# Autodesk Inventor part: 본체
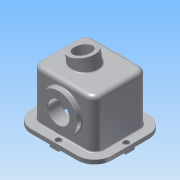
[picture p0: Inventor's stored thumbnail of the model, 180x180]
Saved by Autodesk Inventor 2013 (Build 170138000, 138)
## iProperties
Created: 2014-11
Part Number: 본체
Material: Aluminum 6061
Document SubType Name: Modeling
Designer: Administrator
Density: 2.71 g/cm^3
Mass: 2881.87 g
Surface Area: 2079.03 cm^2
Volume: 1063.42 cm^3
Author: Administrator
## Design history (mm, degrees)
sketch "Sketch1"
  geometry: L1 (-76, 65)-(76, 65); L2 (76, 65)-(76, -65); L3 (76, -65)-(-76, -65); L4 (-76, -65)-(-76, 65); L5 (-76, 65)-(76, -65); L6 (76, 65)-(-76, -65); 1 further point
  constraints: 12 end point, 2 midpoint, 2 parallel, 1 horizontal, 1 perpendicular
  dimensions: "d0" = 152 distance of L2.end L3.end; "d1" = 130 distance of L1.end L2.end
extrude "Extrusion1" new body sketch "Sketch1" distance "d2" = 60; taper "d3" = 0 deg; dims "d88" = 58, "d89" = 0
fillet "Fillet1" dims "d4" = 20
fillet "Fillet2" dims "d5" = 10
shell "Shell1" dims "d6" = 10
sketch "Sketch2"
  geometry: L1 (-66, -45)-(-66, 45) reference; L2 (-56, 55)-(56, 55) reference; L3 (66, 45)-(66, -45) reference; L4 (56, -55)-(-56, -55) reference; L5 (56, 87)-(-56, 87); L6 (-98, 45)-(-98, -45); L7 (-56, -87)-(56, -87); L8 (98, -45)-(98, 45); L9 (98, 87)-(-98, -87); L10 (-98, 87)-(98, -87); A1 r 10 centre (-56, 45) between (-56, 55) and (-66, 45) reference; A2 r 10 centre (56, 45) between (66, 45) and (56, 55) reference; A3 r 10 centre (56, -45) between (56, -55) and (66, -45) reference; A4 r 10 centre (-56, -45) between (-66, -45) and (-56, -55) reference; A5 r 42 centre (56, 45) between (98, 45) and (56, 87); A6 r 42 centre (56, -45) between (56, -87) and (98, -45); A7 r 42 centre (-56, -45) between (-98, -45) and (-56, -87); A8 r 42 centre (-56, 45) between (-56, 87) and (-98, 45); 3 further points
  constraints: 12 end point, 8 point on circle, 8 point on line, 8 tangent, 4 centre point, 3 equal radius, 3 midpoint, 2 parallel, 1 horizontal, 1 horizontal alignment, 1 perpendicular
  dimensions: "d7" = 196 distance of L9.end L10.end; "d9" = 174 distance of L10.start L9.end; "d10" = 42 radius of A5; "d11" = 10 distance from line of point (88, 0) L8
extrude "Extrusion2" join sketch "Sketch2" distance "d12" = 10; taper "d13" = 0 deg
hole "Hole1" sketch "Sketch2" diameter "d14" = 9; stored, may be unused: countersink angle "d18" = 90 deg, drill point angle "d20" = 118 deg; dims "d15" = 6, "d16" = 14, "d17" = 8.6, "d19" = 8
mirror "Mirror1"
workplane "Work Plane1"
sketch "Sketch3"
  geometry: C1 r 45.5 at (0, 0); 1 further point
  constraints: 1 centre point, 1 coincident
  dimensions: "d22" = 91 diameter of C1
extrude "Extrusion3" join sketch "Sketch3" stored distance "d23" = 10; taper "d24" = 0 deg
sketch "Sketch4"
  geometry: C1 r 45.5 at (0, 0) reference; 1 further point
  constraints: 1 vertical alignment
  dimensions: "d25" = 35 distance of C1.centre point (0, -35)
hole "Hole2" sketch "Sketch4" at (0, -35) diameter "d26" = 3.242; stored, may be unused: countersink angle "d30" = 90 deg, drill point angle "d32" = 118 deg; dims "d27" = 13, "d28" = 14, "d29" = 8.6, "d31" = 16
pattern_circular "Circular Pattern1" dims angle "d34" = 360 deg
sketch "Sketch5"
  geometry: L1 (-78, 11)-(-98, 11); L2 (-98, 11)-(-98, -11); L3 (-98, -11)-(-78, -11); L4 (-78, -11)-(-78, 11); L5 (-78, 11)-(-98, -11); L6 (-98, 11)-(-78, -11); L7 (98, 11)-(78, 11); L8 (78, 11)-(78, -11); L9 (78, -11)-(98, -11); L10 (98, -11)-(98, 11); L11 (98, 11)-(78, -11); L12 (78, 11)-(98, -11); C1 r 4.5 at (-88, 0) reference; C2 r 4.5 at (88, 0) reference; 1 further point
  constraints: 24 end point, 4 midpoint, 4 parallel, 2 horizontal, 2 perpendicular
  dimensions: "d36" = 20 distance of L3.end L2.end; "d37" = 22 distance of L2.end L1.end; "d38" = 20 distance of L9.end L8.end; "d39" = 22 distance of L8.end L7.end
extrude "Extrusion4" join sketch "Sketch5" distance "d40" = 5; taper "d41" = 0 deg
sketch "Sketch6"
  geometry: L1 (-56, -87)-(56, -87) reference; 2 further points
  constraints: 1 vertical alignment
  dimensions: "d42" = 10 distance from line of L1 point (0, -77)
hole "Hole3" sketch "Sketch6" at (0, -77) diameter "d43" = 9; stored, may be unused: countersink angle "d47" = 90 deg, drill point angle "d49" = 118 deg; dims "d44" = 13, "d45" = 14, "d46" = 8.6, "d48" = 16
sketch "Sketch7"
  geometry: L1 (11, -67)-(-11, -67); L2 (-11, -67)-(-11, -87); L3 (-11, -87)-(11, -87); L4 (11, -87)-(11, -67); L5 (11, -67)-(-11, -87); L6 (-11, -67)-(11, -87); C1 r 4.5 at (0, -77) reference; 1 further point
  constraints: 12 end point, 2 midpoint, 2 parallel, 1 horizontal, 1 perpendicular
  dimensions: "d50" = 22 distance of L3.end L2.end; "d51" = 20 distance of L2.end L1.end
extrude "Extrusion5" join sketch "Sketch7" distance "d52" = 5; taper "d53" = 0 deg
mirror "Mirror2"
workplane "Work Plane3"
  workplane "Work Plane2"
sketch "Sketch8"
  geometry: C1 r 31 at (0, 0); 1 further point
  constraints: 1 centre point, 1 coincident
  dimensions: "d56" = 62 diameter of C1
extrude "Extrusion6" join sketch "Sketch8" stored distance "d57" = 5; taper "d58" = 0 deg
hole "Hole4" diameter "d61" = 30; stored, may be unused: countersink angle "d65" = 90 deg, drill point angle "d67" = 118 deg; dims "d59" = 10, "d60" = 10, "d62" = 13, "d63" = 42, "d64" = 25, "d66" = 16
sketch "Sketch9"
  geometry: L1 (81.5, -66.6)-(84, -66.6) reference; L2 (84, -66.6)-(84, -58) reference; L3 (84, -58)-(87, -58) reference; L4 (87, -58)-(87, -73) reference; L5 (87, -73)-(81.5, -73) reference; L6 (81.5, -73)-(81.5, -66.6) reference; L7 (-84, -66.6)-(-81.5, -66.6) reference; L8 (-81.5, -66.6)-(-81.5, -73) reference; L9 (-81.5, -73)-(-87, -73) reference; L10 (-87, -73)-(-87, -58) reference; L11 (-87, -58)-(-84, -58) reference; L12 (-84, -58)-(-84, -66.6) reference; L13 (-65, -58)-(-65, 50) reference; L14 (-55, 60)-(-28.379, 60) reference; L15 (-25.037, 87.921)-(-10.337, 87.921) reference; L16 (-16.519, 62.363)-(-7.542, 62.363) reference; L17 (-10.814, 50)-(-55, 50) reference; L18 (-55, 50)-(-55, -68) reference; L19 (-55, -68)-(-67, -68) reference; L20 (-67, -68)-(-67, -73) reference; L21 (-67, -73)-(-72.5, -73) reference; L22 (-72.5, -73)-(-72.5, -66.6) reference; L23 (-72.5, -66.6)-(-70, -66.6) reference; L24 (-70, -66.6)-(-70, -58) reference; L25 (-70, -58)-(-65, -58) reference; L26 (65, 50)-(65, 45.5) reference; L27 (65, 45.5)-(77, 45.5) reference; L28 (77, 45.5)-(77, 36.621) reference; L29 (77, 36.621)-(61, 36.621) reference; L30 (61, 36.621)-(60.026, 35) reference; L31 (60.026, 35)-(61, 33.379) reference; L32 (61, 33.379)-(77, 33.379) reference; L33 (77, 33.379)-(77, -33.379) reference; L34 (77, -33.379)-(61, -33.379) reference; L35 (61, -33.379)-(60.026, -35) reference; L36 (60.026, -35)-(61, -36.621) reference; L37 (61, -36.621)-(77, -36.621) reference; L38 (77, -36.621)-(77, -45.5) reference; L39 (77, -45.5)-(65, -45.5) reference; L40 (65, -45.5)-(65, -58) reference; L41 (65, -58)-(70, -58) reference; L42 (70, -58)-(70, -66.6) reference; L43 (70, -66.6)-(72.5, -66.6) reference; L44 (72.5, -66.6)-(72.5, -73) reference; L45 (72.5, -73)-(67, -73) reference; L46 (67, -73)-(67, -68) reference; L47 (67, -68)-(55, -68) reference; L48 (55, -68)-(55, 50) reference; L49 (55, 50)-(10.814, 50) reference; L50 (7.542, 62.363)-(16.519, 62.363) reference; L51 (10.337, 87.921)-(25.037, 87.921) reference; L52 (28.379, 60)-(55, 60) reference; L53 (55, 0)-(55, 45.5); L54 (55, 45.5)-(45, 35.5); L55 (45, 35.5)-(45, 0); L56 (45, 0)-(55, 0); A1 r 10 centre (-55, 50) between (-55, 60) and (-65, 50) reference; A2 r 10 centre (55, 50) between (65, 50) and (55, 60) reference; 7 further points; 6 other entities
  constraints: 8 end point, 2 perpendicular, 1 horizontal alignment, 1 parallel, 1 vertical alignment, 6 other
  dimensions: "d68" = 91 diameter of L53.end L56; "d70" = 71 diameter of L54.end L56; "d71" = 10 distance between parallel lines of L55 L53
revolve "Revolution1" sketch "Sketch9" stored, may be unused: angle "d72" = 90 deg
sketch "Sketch10"
  geometry: C1 r 45.5 at (0, 0) reference; C2 r 26 at (0, 0)
  constraints: 1 centre point, 1 coincident
  dimensions: "d73" = 52 diameter of C2
extrude "Extrusion7" cut sketch "Sketch10" stored distance "d74" = 5; taper "d75" = 0 deg
mirror "Mirror3"
chamfer "Chamfer2" distance "d80" = 1; stored, may be unused: second distance "d81" = 2, angle "d82" = 45 deg
fillet "Fillet4" dims "d83" = 3
fillet "Fillet5" dims "d84" = 0.3
sketch "Sketch11"
  geometry: L1 (-118, 56)-(-118, 90) reference; 2 further points
  constraints: 1 horizontal alignment, 1 other
  dimensions: "d85" = 92 distance from line of L1 point (-26, 45)
emboss "Emboss1" sketch "Sketch11" dims "d0" = 152, "d1" = 130, "d86" = 1, "d87" = 0
body "Solid1"
node "Project Cut Edges1"
other parameters: "d21" = 77, "d54" = -12 deg, "d55" = 86
